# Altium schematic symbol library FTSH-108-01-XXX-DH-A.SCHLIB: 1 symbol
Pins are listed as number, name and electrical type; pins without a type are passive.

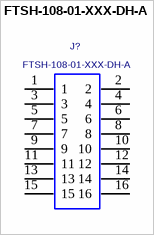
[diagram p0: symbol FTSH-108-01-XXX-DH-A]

## FTSH-108-01-XXX-DH-A
designator J?
.050 X .050 C.L. DOUBLE HORIZONTAL TERMINAL STRIP.; MANUFACTURER: SAMTEC
footprint FTSH-108-01-XXX-DH-A
pins: 1, 2, 3, 4, 5, 6, 7, 8, 9, 10, 11, 12, 13, 14, 15, 16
